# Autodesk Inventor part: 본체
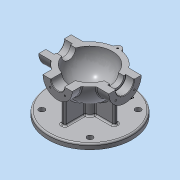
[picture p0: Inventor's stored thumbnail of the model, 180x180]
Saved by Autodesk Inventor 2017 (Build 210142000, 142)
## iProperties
Created: 2015-12
Part Number: 본체
Material: 알루미늄 6061
Document SubType Name: Modeling
Designer: mduedu
Density: 2.71 g/cm^3
Mass: 1042.75 g
Surface Area: 959.747 cm^2
Volume: 384.779 cm^3
Appearance: 알루미늄 - 평지
Author: mduedu
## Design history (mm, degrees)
sketch "스케치1"
  geometry: L1 (-53, 0)-(53, 0); A1 r 53 centre (0, 0) between (53, 0) and (-53, 0); 2 further points
  constraints: 2 coincident, 2 end point, 2 point on circle, 1 centre point, 1 horizontal, 1 midpoint
  dimensions: "d0" = 53 radius of A1
revolve "회전1" sketch "스케치1" stored, may be unused: angle "d2" = 90 deg
feature "쉘1" dims "d11" = 10
node "작업 평면1"
sketch "스케치2"
  geometry: C1 r 31 at (0, 0); 1 further point
  constraints: 1 centre point, 1 coincident
  dimensions: "d4" = 62 diameter of C1
extrude "돌출1" join sketch "스케치2" stored distance "d5" = 10; taper "d6" = 0 deg
node "작업 평면2"
sketch "스케치3"
  geometry: C1 r 28 at (0, 0); 1 further point
  constraints: 1 centre point, 1 coincident
  dimensions: "d8" = 56 diameter of C1
extrude "돌출2" join sketch "스케치3" stored distance "d9" = 10; taper "d10" = 0 deg
hole "구멍1" diameter "d14" = 35; stored, may be unused: countersink angle "d18" = 90 deg, drill point angle "d20" = 0 deg; dims "d12" = 10, "d13" = 10, "d15" = 6, "d16" = 4, "d17" = 2, "d19" = 16
hole "구멍2" diameter "d23" = 27; stored, may be unused: countersink angle "d27" = 90 deg, drill point angle "d29" = 0 deg; dims "d21" = 10, "d22" = 10, "d24" = 6, "d25" = 4, "d26" = 2, "d28" = 16
fillet "모깎기1" dims "d30" = 0.3
hole "구멍3" diameter "d33" = 26; stored, may be unused: countersink angle "d37" = 90 deg, drill point angle "d39" = 0 deg; dims "d31" = 10, "d32" = 10, "d34" = 6, "d35" = 4, "d36" = 2, "d38" = 16
chamfer "모따기1" distance "d40" = 1; stored, may be unused: second distance "d41" = 2, angle "d42" = 45 deg
sketch "스케치4"
  geometry: L1 (0, 0)-(0, -25); L2 (0, 0)-(-17.678, -17.678); A1 r 25 centre (0, 0) between (-17.678, -17.678) and (0, -25); 1 further point
  constraints: 4 end point, 2 point on circle, 1 centre point, 1 coincident, 1 vertical
  dimensions: "d43" = 50 diameter of A1; "d47" = 45 deg angle of L1 L2
hole "구멍4" sketch "스케치4" at (-17.678, -17.678) diameter "d49" = 3.242; stored, may be unused: countersink angle "d53" = 90 deg, drill point angle "d55" = 118 deg; dims "d50" = 11, "d51" = 4, "d52" = 2, "d54" = 13
sketch "스케치5"
  geometry: L1 (0, 0)-(0, -20); L2 (0, 0)-(-14.142, -14.142); A1 r 20 centre (0, 0) between (0, -20) and (-14.142, -14.142); 2 further points
  constraints: 4 end point, 2 coincident, 2 point on circle, 1 centre point, 1 vertical
  dimensions: "d59" = 40 diameter of A1; "d65" = 45 deg angle of L1 L2
hole "구멍5" sketch "스케치5" at (-14.142, -14.142) diameter "d67" = 3.242; stored, may be unused: countersink angle "d71" = 90 deg, drill point angle "d73" = 118 deg; dims "d68" = 8, "d69" = 4, "d70" = 2, "d72" = 10
node "작업 평면3"
sketch "스케치6"
  geometry: C1 r 80 at (0, 0); 1 further point
  constraints: 1 centre point, 1 coincident
  dimensions: "d78" = 160 diameter of C1
extrude "돌출3" join sketch "스케치6" distance "d80" = 10; taper "d81" = 0 deg
sketch "스케치7"
  geometry: C1 r 15 at (0, 0); 1 further point
  constraints: 1 centre point, 1 coincident
  dimensions: "d82" = 30 diameter of C1
extrude "돌출4" join sketch "스케치7" stored distance "d84" = 10; taper "d85" = 0 deg
sketch "스케치8"
  geometry: 2 further points
  constraints: 1 coincident
hole "구멍6" sketch "스케치8" at (0, 0) diameter "d86" = 20; stored, may be unused: countersink angle "d90" = 90 deg, drill point angle "d92" = 118 deg; dims "d87" = 7, "d88" = 100, "d89" = 5, "d91" = 10
fillet "모깎기2" dims "d93" = 0.3
sketch "스케치9"
  geometry: L1 (-67, -18.5)-(-66, -17.5) reference; L2 (-66, -17.5)-(-51.3, -17.5) reference; L3 (-51, -17.2)-(-51, -13.5) reference; L4 (-51, -13.5)-(-40.826, -13.5) reference; L5 (-10, -41.821)-(-10, -80) reference; L6 (-10, -80)-(-49.7, -80) reference; L7 (-50, -80.3)-(-50, -85) reference; L8 (-50, -85)-(-80, -85) reference; L9 (-80, -85)-(-80, -75) reference; L10 (-80, -75)-(-15, -75) reference; L11 (-15, -75)-(-15, -50.833) reference; L12 (-42.988, -31)-(-67, -31) reference; L13 (-67, -31)-(-67, -18.5) reference; L14 (66, -17.5)-(67, -18.5) reference; L15 (67, -18.5)-(67, -31) reference; L16 (67, -31)-(42.988, -31) reference; L17 (15, -50.833)-(15, -75) reference; L18 (15, -75)-(80, -75) reference; L19 (80, -75)-(80, -85) reference; L20 (80, -85)-(50, -85) reference; L21 (50, -85)-(50, -80.3) reference; L22 (49.7, -80)-(10, -80) reference; L23 (10, -80)-(10, -41.821) reference; L24 (40.826, -13.5)-(51, -13.5) reference; L25 (51, -13.5)-(51, -17.2) reference; L26 (51.3, -17.5)-(66, -17.5) reference; L27 (67, 18.5)-(66, 17.5) reference; L28 (66, 17.5)-(51.3, 17.5) reference; L29 (51, 17.2)-(51, 13.5) reference; L30 (51, 13.5)-(40.826, 13.5) reference; L31 (-40.826, 13.5)-(-51, 13.5) reference; L32 (-51, 13.5)-(-51, 17.2) reference; L33 (-51.3, 17.5)-(-66, 17.5) reference; L34 (-66, 17.5)-(-67, 18.5) reference; L35 (-67, 18.5)-(-67, 31) reference; L36 (-67, 31)-(-42.988, 31) reference; L37 (42.988, 31)-(67, 31) reference; L38 (67, 31)-(67, 18.5) reference; L39 (-50, -31)-(-50, -75); A1 r 0.3 centre (-51.3, -17.2) between (-51.3, -17.5) and (-51, -17.2) reference; A2 r 43 centre (0, 0) between (-40.826, -13.5) and (-10, -41.821) reference; A3 r 0.3 centre (-49.7, -80.3) between (-49.7, -80) and (-50, -80.3) reference; A4 r 53 centre (0, 0) between (-42.988, -31) and (-15, -50.833) reference; A5 r 53 centre (0, 0) between (15, -50.833) and (42.988, -31) reference; A6 r 0.3 centre (49.7, -80.3) between (50, -80.3) and (49.7, -80) reference; A7 r 43 centre (0, 0) between (10, -41.821) and (40.826, -13.5) reference; A8 r 0.3 centre (51.3, -17.2) between (51, -17.2) and (51.3, -17.5) reference; A9 r 0.3 centre (51.3, 17.2) between (51.3, 17.5) and (51, 17.2) reference; A10 r 43 centre (0, 0) between (40.826, 13.5) and (-40.826, 13.5) reference; A11 r 0.3 centre (-51.3, 17.2) between (-51, 17.2) and (-51.3, 17.5) reference; A12 r 53 centre (0, 0) between (42.988, 31) and (-42.988, 31) reference; 1 further point
  constraints: 2 end point, 2 point on line
  dimensions: "d173" = 30 distance from line of L39.end L9; "d174" = 90 deg angle of L10 L39
feature "리브1" sketch "스케치9" dims "d96" = 1, "d97" = 8, "d98" = 0, "d99" = 0, "d100" = 1, "d101" = 1
sketch "스케치14"
  geometry: L1 (-14, 62)-(-13, 61) reference; L2 (-13, 61)-(-13, 40.988) reference; L3 (-41.821, 10)-(-80, 10) reference; L4 (-80, 10)-(-80, 49.7) reference; L5 (-80.3, 50)-(-85, 50) reference; L6 (-85, 50)-(-85, 80) reference; L7 (-85, 80)-(-75, 80) reference; L8 (-75, 80)-(-75, 15) reference; L9 (-75, 15)-(-50.833, 15) reference; L10 (-28, 45)-(-28, 62) reference; L11 (-28, 62)-(-14, 62) reference; L12 (13, 61)-(14, 62) reference; L13 (14, 62)-(28, 62) reference; L14 (28, 62)-(28, 45) reference; L15 (-50.833, -15)-(-75, -15) reference; L16 (-75, -15)-(-75, -80) reference; L17 (-75, -80)-(-85, -80) reference; L18 (-85, -80)-(-85, -50) reference; L19 (-85, -50)-(-80.3, -50) reference; L20 (-80, -49.7)-(-80, -10) reference; L21 (-80, -10)-(-41.821, -10) reference; L22 (13, 40.988)-(13, 61) reference; L23 (-28, 52)-(-75, 52); A1 r 43 centre (0, 0) between (-13, 40.988) and (-41.821, 10) reference; A2 r 0.3 centre (-80.3, 49.7) between (-80, 49.7) and (-80.3, 50) reference; A3 r 53 centre (0, 0) between (-28, 45) and (-50.833, 15) reference; A4 r 53 centre (0, 0) between (0, -53) and (28, 45) reference; A5 r 53 centre (0, 0) between (-50.833, -15) and (0, -53) reference; A6 r 0.3 centre (-80.3, -49.7) between (-80.3, -50) and (-80, -49.7) reference; A7 r 43 centre (0, 0) between (-41.821, -10) and (0, -43) reference; A8 r 43 centre (0, 0) between (0, -43) and (13, 40.988) reference; 1 further point
  constraints: 2 end point, 2 point on line
  dimensions: "d175" = 28 distance of L7.end L23.end; "d176" = 90 deg angle of L8 L23
feature "리브2" sketch "스케치14" dims "d153" = 1, "d154" = 8, "d155" = 0, "d156" = 0, "d157" = 1, "d158" = 1
sketch "스케치10"
  geometry: L1 (0, 0)-(0, -65); L2 (0, 0)-(-45.962, -45.962); A1 r 65 centre (0, 0) between (0, -65) and (-45.962, -45.962); 2 further points
  constraints: 4 end point, 2 coincident, 2 point on circle, 1 centre point, 1 vertical
  dimensions: "d105" = 130 diameter of A1; "d107" = 45 deg angle of L1 L2
hole "구멍7" sketch "스케치10" at (-45.962, -45.962) diameter "d109" = 11; stored, may be unused: countersink angle "d113" = 90 deg, drill point angle "d115" = 118 deg; dims "d110" = 7, "d111" = 18, "d112" = 4, "d114" = 10
fillet "모깎기3" dims "d120" = 3
fillet "모깎기4" dims "d121" = 3, "d122" = 3
fillet "모깎기5" dims "d123" = 3
fillet "모깎기6" dims "d124" = 3
sketch "스케치11"
  geometry: C1 r 80 at (0, 0) reference; C2 r 65 at (0, 0)
  constraints: 1 centre point, 1 coincident, 1 other
  dimensions: "d161" = 130 diameter of C2
feature "엠보싱1" sketch "스케치11" dims "d11" = 10, "d125" = 0.5, "d126" = 0
sketch "스케치12"
  geometry: L1 (0, 100)-(0, -100); L2 (0, 100)-(100, 100); L3 (100, 100)-(100, -100); L4 (100, -100)-(0, -100); 2 further points
  constraints: 8 end point, 3 perpendicular, 1 coincident, 1 midpoint, 1 vertical
  dimensions: "d127" = 200 distance of L2.end L3.end; "d129" = 100 distance between parallel lines of L1 L3
extrude "돌출5" cut sketch "스케치12" stored distance "d130" = 10; taper "d131" = 0 deg
sketch "스케치13"
  geometry: C1 r 7 at (0, 53); A1 r 53 centre (0, 0) between (42.113, 32.179) and (-42.113, 32.179) reference; 1 further point
  constraints: 1 centre point, 1 point on circle
  dimensions: "d132" = 14 diameter of C1
extrude "돌출6" join sketch "스케치13" distance "d134" = 15; taper "d135" = 0 deg
hole "구멍8" diameter "d139" = 3.242; stored, may be unused: countersink angle "d143" = 90 deg, drill point angle "d145" = 118 deg; dims "d140" = 8, "d141" = 4, "d142" = 2, "d144" = 10, "d148" = 10, "d149" = 10
fillet "모깎기7" dims "d146" = 3
fillet "모깎기8" dims "d147" = 3
node "솔리드1"
mirror "대칭1"
mirror "대칭2"
pattern_circular "원형 패턴1" dims angle "d57" = 360 deg
mirror "대칭3"
pattern_circular "원형 패턴2" dims angle "d75" = 360 deg
mirror "대칭4"
pattern_circular "원형 패턴4" dims angle "d118" = 360 deg
node "절단 모서리 투영1"
node "절단 모서리 투영2"
other parameters: "d3" = 67, "d7" = 62, "d77" = -85
